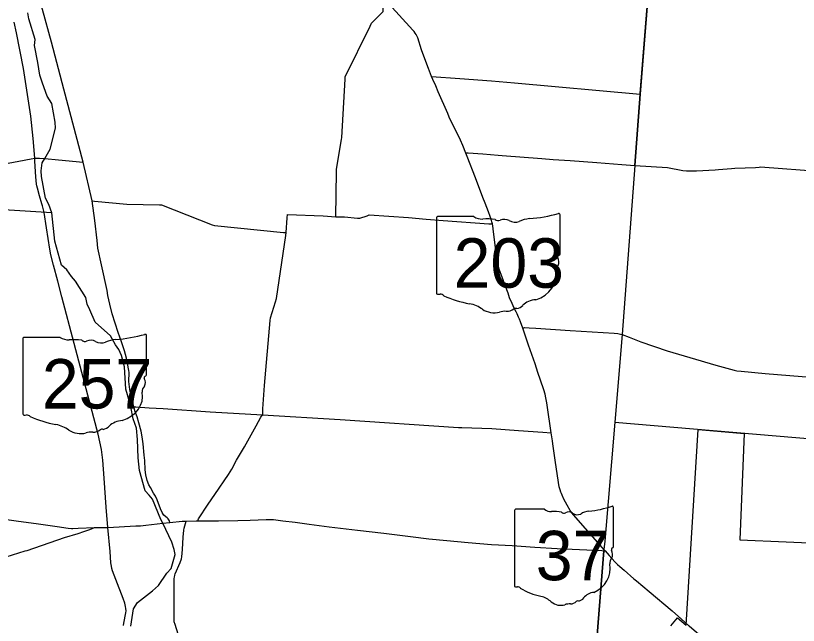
# Model space of a CAD drawing. Extents: x 1729596 to 1925846, y 659247 to 911751.
# Drawn here: x 1777664 to 1799698, y 843541 to 860705 of the extents above; entities that cross this region are included whole.
import ezdxf

# ---------------------------------------------------------------- set-up
doc = ezdxf.new("R2010")
doc.units = 0
for name, color, linetype in [('GM_X_Corporation', 7, 'Continuous'), ('GM_X_County_Road', 7, 'Continuous'), ('GM_X_State_Route', 7, 'Continuous'), ('GM_X_State_Shield', 7, 'Continuous'), ('GM_X_Township', 7, 'Continuous'), ('GM_X_Township_Road', 7, 'Continuous')]:
    doc.layers.add(name, color=color, linetype=linetype)

msp = doc.modelspace()

# ---------------------------------------------------------------- linework, layer by layer
at = {"layer": 'GM_X_Corporation'}
msp.add_lwpolyline([(1796105, 843523), (1796297, 843753), (1796540, 843550), (1796878, 849051), (1798177, 848946), (1798053, 845944), (1800661, 845836)], dxfattribs=at)
at = {"layer": 'GM_X_County_Road'}
for points in [[(1779569, 856584), (1779019, 858639), (1778669, 859959), (1778417, 860876), (1778136, 861918), (1778010, 862427), (1777970, 862741)], [(1786675, 855044), (1786697, 856311), (1786698, 856387), (1786835, 857221), (1786845, 857279), (1786936, 858914), (1786940, 858987), (1787642, 860408), (1787683, 860493), (1787941, 860759), (1788006, 860826), (1788012, 861039), (1788018, 861131), (1788033, 861371)], [(1774515, 855940), (1775597, 856145), (1775681, 856161), (1777256, 856513), (1778103, 856674), (1778201, 856693), (1778256, 856697), (1778340, 856696), (1778464, 856683)], [(1778464, 856683), (1778481, 856682), (1778870, 856644), (1779569, 856584)], [(1779821, 855489), (1779569, 856584)], [(1779821, 855489), (1779879, 855478), (1780796, 855402), (1781715, 855381), (1781774, 855378), (1783200, 854819), (1783259, 854796), (1785203, 854604), (1785283, 854596)], [(1782794, 846480), (1782798, 846516), (1782808, 846543), (1783085, 846950), (1783272, 847226), (1783653, 847787), (1783748, 847942), (1783883, 848187), (1784102, 848564), (1784433, 849156), (1784568, 849404), (1784612, 849472), (1784619, 849495), (1784625, 849639), (1784668, 850295), (1784833, 852121), (1784839, 852194), (1784977, 852649), (1785005, 852740), (1785271, 854516), (1785283, 854596), (1785312, 855017), (1785318, 855106), (1786321, 855070), (1786675, 855044), (1786776, 855041), (1786778, 855041)], [(1786778, 855041), (1786924, 855037), (1787292, 855007), (1787356, 855002), (1787555, 855074), (1787618, 855096), (1788721, 855019), (1789216, 854979), (1789701, 854941), (1790989, 854849), (1791087, 854843)], [(1793847, 840780), (1793954, 842199), (1794218, 845643)]]:
    msp.add_lwpolyline(points, dxfattribs=at)
at = {"layer": 'GM_X_State_Route'}
for points in [[(1794187, 845719), (1793434, 846579), (1793324, 846710), (1793274, 846777), (1793187, 846924), (1793100, 847093), (1793045, 847210), (1793027, 847252), (1793013, 847289), (1792991, 847355), (1792967, 847443), (1792946, 847558), (1792850, 848193), (1792784, 848652), (1792773, 848731), (1792740, 848959), (1792628, 849742), (1792619, 849803), (1792592, 849950), (1792568, 850047), (1792530, 850174), (1792441, 850445), (1792367, 850662), (1792285, 850899), (1792105, 851429), (1791940, 851905), (1791877, 852084), (1791846, 852163), (1791822, 852220), (1791780, 852313), (1791755, 852366), (1791702, 852474), (1791642, 852598), (1791571, 852765), (1791525, 852890), (1791444, 853113), (1791397, 853241), (1791277, 853572), (1791258, 853631), (1791244, 853685), (1791226, 853784), (1791205, 853939), (1791111, 854702), (1791100, 854784), (1791087, 854843), (1791073, 854900), (1791061, 854942), (1791021, 855052), (1790974, 855179), (1790879, 855426), (1790817, 855588), (1790721, 855839), (1790647, 856032), (1790607, 856138), (1790378, 856737), (1790341, 856833), (1790254, 857050), (1790190, 857197), (1790044, 857488), (1789945, 857688), (1789872, 857851), (1789828, 857951), (1789562, 858562), (1789490, 858725), (1789407, 858912), (1789372, 858995), (1789284, 859215), (1789180, 859492), (1789091, 859742), (1788985, 860077), (1788969, 860118), (1788940, 860175), (1788914, 860215), (1788880, 860256), (1788847, 860293), (1788174, 861037)], [(1780260, 846299), (1780214, 846871), (1780156, 847683), (1780119, 848192), (1780103, 848341), (1780082, 848490), (1780037, 848711), (1779990, 848921), (1779866, 849386), (1779314, 851479), (1778967, 852787), (1778849, 853232), (1778732, 853677), (1778659, 853968), (1778625, 854134), (1778535, 854732), (1778466, 855163), (1778422, 855348), (1778404, 855403), (1778338, 855632), (1778279, 855845), (1778264, 855913), (1778254, 855963), (1778240, 856063), (1778232, 856164), (1778207, 856610), (1778201, 856693), (1778158, 857245), (1778089, 857871), (1777889, 859222), (1777685, 860217), (1777620, 860525)], [(1776476, 846710), (1776545, 846695), (1777099, 846577), (1777213, 846553), (1777679, 846483), (1778305, 846395), (1778834, 846323), (1779138, 846279), (1779232, 846271), (1779274, 846270), (1779424, 846274), (1779888, 846291), (1780260, 846299)], [(1780260, 846299), (1780260, 846299), (1781047, 846338), (1781176, 846347), (1781331, 846363), (1781806, 846413), (1782009, 846435), (1782350, 846472), (1782467, 846475), (1782747, 846479)], [(1782747, 846479), (1782794, 846480), (1783183, 846484), (1783377, 846485), (1783923, 846492), (1784269, 846503), (1784713, 846520), (1784920, 846517), (1785189, 846487), (1785532, 846441), (1785928, 846388), (1786488, 846310), (1787292, 846217), (1788027, 846133), (1788780, 846042), (1789296, 845980), (1789805, 845926), (1790403, 845872), (1791058, 845819), (1791646, 845786), (1792283, 845741), (1792907, 845707), (1794165, 845645)], [(1780704, 843535), (1780710, 843602), (1780766, 843894), (1780771, 843954), (1780769, 844015), (1780761, 844075), (1780737, 844162), (1780688, 844296), (1780481, 844827), (1780394, 845075), (1780375, 845141), (1780363, 845204), (1780347, 845305), (1780320, 845620), (1780260, 846299)], [(1794256, 845640), (1794225, 845677), (1794187, 845719)], [(1794165, 845645), (1794218, 845643), (1794256, 845640)], [(1794256, 845640), (1794372, 845506), (1794532, 845328), (1794610, 845252), (1794673, 845195), (1794795, 845090), (1795070, 844854), (1795139, 844795), (1795501, 844493), (1796141, 843947), (1796409, 843716), (1796609, 843541)], [(1796609, 843541), (1796627, 843525), (1796897, 843295), (1796897, 843295)]]:
    msp.add_lwpolyline(points, dxfattribs=at)
at = {"layer": 'GM_X_State_Shield'}
for p, q in [((1789509, 855011), (1789509, 852897)), ((1789509, 855011), (1789509, 852897)), ((1790562, 855047), (1789543, 855047)), ((1790562, 855047), (1789543, 855047)), ((1792989, 853994), (1792989, 855099)), ((1792989, 853994), (1792989, 855099)), ((1792989, 853994), (1792989, 853994)), ((1792989, 853994), (1792989, 853994)), ((1777866, 851609), (1777866, 849496)), ((1777866, 851609), (1777866, 849496)), ((1778920, 851646), (1777901, 851646)), ((1778920, 851646), (1777901, 851646)), ((1781347, 850593), (1781347, 851698)), ((1781347, 850593), (1781347, 851698)), ((1781346, 850593), (1781347, 850593)), ((1781346, 850593), (1781347, 850593)), ((1791706, 846774), (1791706, 844660)), ((1791706, 846774), (1791706, 844660)), ((1792549, 846810), (1791733, 846810)), ((1792549, 846810), (1791733, 846810)), ((1794490, 845757), (1794490, 846862)), ((1794490, 845757), (1794490, 846862)), ((1794490, 845757), (1794490, 845757)), ((1794490, 845757), (1794490, 845757))]:
    msp.add_line(p, q, dxfattribs=at)
for centre, radius, start, end in [((1791738, 846778), 32.3, 98.1301, 188.1301), ((1791738, 846778), 32.3, 98.1301, 188.1301), ((1792743, 847055), 313, 231.6195, 271.1119), ((1792743, 847055), 313, 231.6195, 271.1119), ((1793498, 849691), 2953, 275.8445, 288.9065), ((1793498, 849691), 2953, 275.8445, 288.9065), ((1794459, 846867), 31, 351.8621, 97.738), ((1794459, 846867), 31, 351.8621, 97.738), ((1792846, 845624), 1123, 80.4867, 94.9883), ((1792846, 845624), 1123, 80.4867, 94.9883), ((1793101, 846789), 90.3, 219.7921, 297.1024), ((1793101, 846789), 90.3, 219.7921, 297.1024), ((1793234, 846545), 188, 54.4667, 119.1411), ((1793234, 846545), 188, 54.4667, 119.1411), ((1793476, 846880), 226, 233.8562, 294.8282), ((1793476, 846880), 226, 233.8562, 294.8282), ((1793875, 846165), 594, 97.3462, 120.7689), ((1793875, 846165), 594, 97.3462, 120.7689), ((1794483, 845676), 48, 107.944, 210.337), ((1794483, 845676), 48, 107.944, 210.337), ((1794457, 845753), 33.2, 289.6038, 7.7341), ((1794457, 845753), 33.2, 289.6038, 7.7341), ((1794601, 845294), 210, 136.8065, 186.9296), ((1794601, 845294), 210, 136.8065, 186.9296), ((1794178, 845536), 288, 340.033, 23.6496), ((1794178, 845536), 288, 340.033, 23.6496), ((1793664, 845154), 739, 292.3089, 8.9858), ((1793664, 845154), 739, 292.3089, 8.9858), ((1791738, 844656), 32.5, 171.9584, 258.3066), ((1791738, 844656), 32.5, 171.9584, 258.3066), ((1791743, 844872), 248, 267.339, 280.6039), ((1791743, 844872), 248, 267.339, 280.6039), ((1791794, 844539), 89.5, 29.7484, 93.2717), ((1791794, 844539), 89.5, 29.7484, 93.2717), ((1792924, 846437), 2132, 240.4129, 257.1985), ((1792924, 846437), 2132, 240.4129, 257.1985), ((1792288, 843711), 667, 47.1842, 75.836), ((1792288, 843711), 667, 47.1842, 75.836), ((1793975, 844067), 404, 94.4031, 142.5768), ((1793975, 844067), 404, 94.4031, 142.5768), ((1793010, 844528), 423, 230.7004, 286.2918), ((1793010, 844528), 423, 230.7004, 286.2918), ((1793255, 843797), 348, 85.6951, 111.2099), ((1793255, 843797), 348, 85.6951, 111.2099), ((1793286, 844370), 226, 268.777, 315.5493), ((1793286, 844370), 226, 268.777, 315.5493), ((1793490, 844165), 63.5, 65.7517, 132.6484), ((1793490, 844165), 63.5, 65.7517, 132.6484), ((1793463, 844456), 239, 282.8732, 323.2771), ((1793463, 844456), 239, 282.8732, 323.2771)]:
    msp.add_arc(centre, radius, start, end, dxfattribs=at)
for centre, major_axis, start_param, end_param in [((1791749, 857928), (3691, 0), 4.814394, 5.042369), ((1791749, 857928), (3691, 0), 4.814394, 5.042369), ((1792950, 855104), (38.7, 0), 6.141152, 7.989035), ((1792950, 855104), (38.7, 0), 6.141152, 7.989035), ((1789548, 855015), (40.3, 0), 1.712693, 3.28349), ((1789548, 855015), (40.3, 0), 1.712693, 3.28349), ((1790805, 855292), (391, 0), 4.042523, 4.731795), ((1790805, 855292), (391, 0), 4.042523, 4.731795), ((1790935, 853860), (1404, 0), 1.404758, 1.657858), ((1790935, 853860), (1404, 0), 1.404758, 1.657858), ((1791253, 855026), (113, 0), 3.836095, 5.185415), ((1791253, 855026), (113, 0), 3.836095, 5.185415), ((1791419, 854782), (235, 0), 0.950623, 2.079405), ((1791419, 854782), (235, 0), 0.950623, 2.079405), ((1791722, 855117), (282, 0), 4.081561, 5.145723), ((1791722, 855117), (282, 0), 4.081561, 5.145723), ((1792220, 854401), (743, 0), 1.699011, 2.107814), ((1792220, 854401), (743, 0), 1.699011, 2.107814), ((1792980, 853913), (60, 0), 1.883978, 3.671073), ((1792980, 853913), (60, 0), 1.883978, 3.671073), ((1792599, 853773), (360, 0), 5.934695, 6.695948), ((1792599, 853773), (360, 0), 5.934695, 6.695948), ((1792948, 853990), (41.5, 0), 5.05454, 6.418171), ((1792948, 853990), (41.5, 0), 5.05454, 6.418171), ((1793128, 853531), (262, 0), 2.387724, 3.262537), ((1793128, 853531), (262, 0), 2.387724, 3.262537), ((1791956, 853391), (923, 0), 5.101752, 6.440018), ((1791956, 853391), (923, 0), 5.101752, 6.440018), ((1789549, 852893), (40.7, 0), 3.00124, 4.508301), ((1789549, 852893), (40.7, 0), 3.00124, 4.508301), ((1789555, 853109), (310, 0), 4.665946, 4.897461), ((1789555, 853109), (310, 0), 4.665946, 4.897461), ((1789619, 852775), (112, 0), 0.519207, 1.627899), ((1789619, 852775), (112, 0), 0.519207, 1.627899), ((1791032, 854674), (2665, 0), 4.195997, 4.488961), ((1791032, 854674), (2665, 0), 4.195997, 4.488961), ((1792345, 852304), (506, 0), 1.647645, 2.488434), ((1792345, 852304), (506, 0), 1.647645, 2.488434), ((1790237, 851948), (834, 0), 0.823519, 1.323587), ((1790237, 851948), (834, 0), 0.823519, 1.323587), ((1791705, 852692), (298, 0), 4.937069, 5.64225), ((1791705, 852692), (298, 0), 4.937069, 5.64225), ((1791139, 852765), (529, 0), 4.026481, 4.996735), ((1791139, 852765), (529, 0), 4.026481, 4.996735), ((1791445, 852034), (435, 0), 1.495662, 1.94098), ((1791445, 852034), (435, 0), 1.495662, 1.94098), ((1791483, 852607), (282, 0), 4.691044, 5.507374), ((1791483, 852607), (282, 0), 4.691044, 5.507374), ((1791739, 852402), (79.4, 0), 1.147584, 2.315152), ((1791739, 852402), (79.4, 0), 1.147584, 2.315152), ((1777906, 851614), (40.3, 0), 1.712693, 3.28349), ((1777906, 851614), (40.3, 0), 1.712693, 3.28349), ((1779162, 851891), (391, 0), 4.042523, 4.731795), ((1779162, 851891), (391, 0), 4.042523, 4.731795), ((1780107, 854527), (3691, 0), 4.814394, 5.042369), ((1780107, 854527), (3691, 0), 4.814394, 5.042369), ((1781308, 851703), (38.7, 0), 6.141152, 7.989035), ((1781308, 851703), (38.7, 0), 6.141152, 7.989035), ((1779292, 850459), (1404, 0), 1.404758, 1.657858), ((1779292, 850459), (1404, 0), 1.404758, 1.657858), ((1779611, 851625), (113, 0), 3.836095, 5.185415), ((1779611, 851625), (113, 0), 3.836095, 5.185415), ((1779777, 851381), (235, 0), 0.950623, 2.079405), ((1779777, 851381), (235, 0), 0.950623, 2.079405), ((1780079, 851716), (282, 0), 4.081561, 5.145723), ((1780079, 851716), (282, 0), 4.081561, 5.145723), ((1780578, 851000), (743, 0), 1.699011, 2.107814), ((1780578, 851000), (743, 0), 1.699011, 2.107814), ((1781338, 850511), (60, 0), 1.883978, 3.671073), ((1781338, 850511), (60, 0), 1.883978, 3.671073), ((1781305, 850588), (41.5, 0), 5.05454, 6.418171), ((1781305, 850588), (41.5, 0), 5.05454, 6.418171), ((1780956, 850372), (360, 0), 5.934695, 6.695948), ((1780956, 850372), (360, 0), 5.934695, 6.695948), ((1780314, 849989), (923, 0), 5.101752, 6.440018), ((1780314, 849989), (923, 0), 5.101752, 6.440018), ((1781485, 850130), (262, 0), 2.387724, 3.262537), ((1781485, 850130), (262, 0), 2.387724, 3.262537), ((1777906, 849491), (40.7, 0), 3.00124, 4.508301), ((1777906, 849491), (40.7, 0), 3.00124, 4.508301), ((1777913, 849708), (310, 0), 4.665946, 4.897461), ((1777913, 849708), (310, 0), 4.665946, 4.897461), ((1777976, 849374), (112, 0), 0.519207, 1.627899), ((1777976, 849374), (112, 0), 0.519207, 1.627899), ((1779389, 851273), (2665, 0), 4.195997, 4.488961), ((1779389, 851273), (2665, 0), 4.195997, 4.488961), ((1778595, 848547), (834, 0), 0.823519, 1.323587), ((1778595, 848547), (834, 0), 0.823519, 1.323587), ((1780703, 848903), (506, 0), 1.647645, 2.488434), ((1780703, 848903), (506, 0), 1.647645, 2.488434), ((1779497, 849364), (529, 0), 4.026481, 4.996735), ((1779497, 849364), (529, 0), 4.026481, 4.996735), ((1779802, 848633), (435, 0), 1.495662, 1.94098), ((1779802, 848633), (435, 0), 1.495662, 1.94098), ((1779841, 849205), (282, 0), 4.691044, 5.507374), ((1779841, 849205), (282, 0), 4.691044, 5.507374), ((1780096, 849001), (79.4, 0), 1.147584, 2.315152), ((1780096, 849001), (79.4, 0), 1.147584, 2.315152), ((1780062, 849291), (298, 0), 4.937069, 5.64225), ((1780062, 849291), (298, 0), 4.937069, 5.64225)]:
    msp.add_ellipse(centre, major_axis=major_axis, ratio=0.8, start_param=start_param, end_param=end_param, dxfattribs=at)
at = {"layer": 'GM_X_Township'}
for points in [[(1795573, 862604), (1795247, 858499), (1795090, 856488), (1794738, 851729), (1794528, 849265), (1794250, 845913), (1794225, 845677), (1794218, 845643), (1793954, 842199)], [(1780907, 843520), (1780980, 844003), (1781094, 844181), (1781518, 844515), (1781682, 844666), (1781918, 845013), (1782045, 845142), (1782155, 845534), (1782125, 845674), (1782062, 845883), (1781806, 846413), (1781752, 846525), (1781519, 847094), (1781420, 847210), (1781308, 847324), (1781148, 847901), (1781109, 848257), (1781090, 848776), (1781068, 849092), (1780971, 849357), (1780904, 849691), (1780816, 850027), (1780762, 850186), (1780725, 850820), (1780641, 851138), (1780564, 851310), (1780471, 851440), (1780333, 851692), (1779900, 852077), (1779756, 852426), (1779678, 852587), (1779637, 852766), (1779349, 853231), (1779232, 853362), (1779109, 853545), (1778954, 853677), (1778765, 854353), (1778678, 855150), (1778601, 855389), (1778502, 855569), (1778390, 856177), (1778385, 856340), (1778415, 856566), (1778481, 856682), (1778631, 856948), (1778790, 857538), (1778777, 857706), (1778686, 858229), (1778551, 858440), (1778417, 858800), (1778344, 859030), (1778284, 859383), (1778195, 859863), (1778212, 860031), (1778036, 860617), (1778010, 860785)], [(1778678, 855150), (1775377, 855361), (1769242, 855826), (1761265, 856432), (1759514, 856565)], [(1794528, 849265), (1800736, 848740), (1801113, 848728), (1805038, 848430), (1809012, 848241), (1810328, 848152), (1816586, 847751), (1820950, 847472)]]:
    msp.add_lwpolyline(points, dxfattribs=at)
at = {"layer": 'GM_X_Township_Road'}
for points in [[(1795248, 858510), (1795573, 862604)], [(1789372, 858995), (1790171, 858935), (1791063, 858867), (1791706, 858811), (1795247, 858499)], [(1795090, 856488), (1795247, 858499), (1795248, 858510)], [(1790341, 856833), (1790361, 856840), (1790407, 856844), (1790813, 856811), (1791251, 856773), (1791363, 856765), (1792476, 856688), (1792792, 856660), (1793270, 856623), (1794021, 856567), (1794727, 856514), (1795090, 856488)], [(1795090, 856488), (1796016, 856428), (1796449, 856346), (1796551, 856339), (1796604, 856337), (1796665, 856335), (1796771, 856339), (1796829, 856341), (1797357, 856367), (1797448, 856371), (1797816, 856403), (1797914, 856411), (1798495, 856434), (1798591, 856437), (1798633, 856451), (1800371, 856321), (1800474, 856313), (1801054, 856281), (1801112, 856277), (1801481, 856249), (1801549, 856244)], [(1782009, 846435), (1781994, 846482), (1781973, 846515), (1781956, 846538), (1781929, 846565), (1781890, 846597), (1781839, 846644), (1781814, 846675), (1781792, 846718), (1781744, 846822), (1781649, 847077), (1781600, 847179), (1781548, 847266), (1781457, 847417), (1781415, 847493), (1781364, 847615), (1781331, 847781), (1781312, 847922), (1781300, 848183), (1781284, 848331), (1781251, 848655), (1781227, 848848), (1781196, 849012), (1781134, 849243), (1781087, 849407), (1781028, 849552), (1780989, 849690), (1780954, 849823), (1780912, 849990), (1780877, 850183), (1780851, 850403), (1780857, 850663), (1780848, 850718), (1780780, 851064), (1780725, 851272), (1780652, 851494), (1780597, 851656), (1780552, 851786), (1780381, 852308), (1780317, 852579), (1780262, 852823), (1780236, 852965), (1780083, 853686), (1779980, 854155), (1779958, 854372), (1779890, 854936), (1779821, 855489)], [(1791940, 851905), (1791969, 851918), (1791991, 851922), (1792120, 851917), (1792308, 851904), (1793274, 851846), (1794516, 851767), (1794619, 851757), (1794724, 851732)], [(1794724, 851732), (1794738, 851729), (1794935, 851656), (1795122, 851581), (1795265, 851527), (1796002, 851268), (1796641, 851079), (1797379, 850870), (1797893, 850723), (1797966, 850705), (1798085, 850695), (1798763, 850635), (1800156, 850514), (1800763, 850469), (1801182, 850439), (1801250, 850449)], [(1780989, 849690), (1781043, 849696), (1781425, 849669), (1781815, 849644), (1783144, 849553), (1784612, 849472)], [(1784612, 849472), (1786799, 849340), (1790129, 849115), (1790221, 849109), (1791065, 849081), (1791820, 849028), (1792506, 848978), (1792740, 848959)], [(1782382, 842844), (1782151, 843564), (1782126, 843641), (1782122, 844417), (1782128, 844831), (1782131, 844863), (1782135, 844894), (1782148, 844956), (1782159, 844992), (1782295, 845310), (1782307, 845335), (1782325, 845387), (1782332, 845413), (1782342, 845467), (1782359, 845678), (1782380, 846027), (1782397, 846217), (1782411, 846275), (1782467, 846475)], [(1773117, 844144), (1774403, 844551), (1774819, 844683), (1776619, 845225), (1776675, 845242), (1777936, 845634), (1777990, 845650), (1779036, 846015), (1779423, 846131), (1779582, 846185), (1779752, 846241), (1779888, 846291)]]:
    msp.add_lwpolyline(points, dxfattribs=at)

# ---------------------------------------------------------------- texts
at = {"layer": 'GM_X_State_Shield'}
for s, p in [('203', (1789994, 853046)), ('203', (1789994, 853046)), ('257', (1778402, 849645)), ('257', (1778402, 849645)), ('37', (1792306, 844810)), ('37', (1792306, 844810))]:
    msp.add_text(s, height=1392.2, dxfattribs=at).set_placement(p)

doc.saveas('drawing.dxf')
